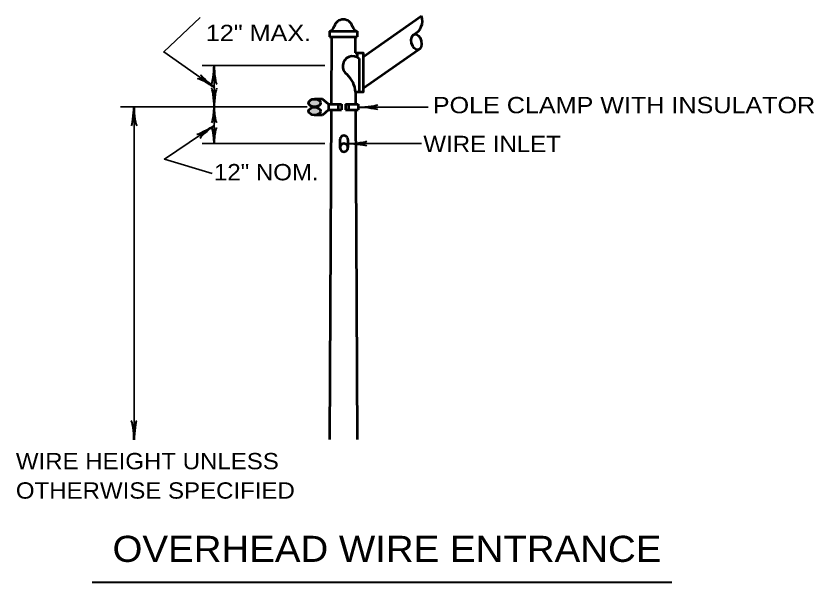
# Model space of a CAD drawing. Extents: x 6488 to 7168, y 276 to 716.
# Drawn here: x 6808.6 to 6930.7, y 441.6 to 528.3 of the extents above; entities that cross this region are included whole.
import ezdxf

# ---------------------------------------------------------------- set-up
doc = ezdxf.new("R2010")
doc.units = 0
doc.layers.add('1', color=7, linetype='Continuous', lineweight=35)

msp = doc.modelspace()

# ---------------------------------------------------------------- hatches: boundary and pattern name
at = {"layer": '1'}
h = msp.add_hatch(color=256, dxfattribs=at)
edge = h.paths.add_edge_path()
edge.add_ellipse((6854.294, 514.969), major_axis=(0.907, 0), ratio=0.6666667, start_angle=0, end_angle=360)
h = msp.add_hatch(color=256, dxfattribs=at)
edge = h.paths.add_edge_path()
edge.add_ellipse((6854.294, 513.717), major_axis=(0.907, 0), ratio=0.6666667, start_angle=0, end_angle=360)

# ---------------------------------------------------------------- linework, layer by layer
at = {"layer": '1', "lineweight": 53}
for p, q in [((6861.725, 522.056), (6870.645, 528.296)), ((6856.586, 525.976), (6860.805, 525.976)), ((6856.586, 525.976), (6856.586, 525.076)), ((6860.805, 525.976), (6860.805, 525.076)), ((6856.586, 525.076), (6860.805, 525.076)), ((6856.885, 525.076), (6856.825, 514.796)), ((6860.506, 525.076), (6860.525, 522.656)), ((6861.725, 517.216), (6870.166, 523.116)), ((6860.825, 522.656), (6860.825, 521.956)), ((6861.126, 521.756), (6861.126, 516.616)), ((6855.506, 515.576), (6854.285, 515.576)), ((6856.425, 514.796), (6855.506, 515.576)), ((6860.546, 516.616), (6860.565, 514.796)), ((6856.425, 514.796), (6858.405, 514.796)), ((6856.425, 514.796), (6856.425, 513.896)), ((6857.905, 514.796), (6857.905, 513.896)), ((6858.405, 514.796), (6858.405, 513.896)), ((6859.006, 514.796), (6860.965, 514.796)), ((6859.006, 514.796), (6859.006, 513.896)), ((6859.485, 514.796), (6859.485, 513.896)), ((6860.965, 514.796), (6860.965, 513.896)), ((6855.506, 513.116), (6854.285, 513.116)), ((6856.425, 513.896), (6855.506, 513.116)), ((6856.425, 513.896), (6858.405, 513.896)), ((6856.825, 513.896), (6856.586, 463.396)), ((6859.006, 513.896), (6860.965, 513.896)), ((6860.565, 513.896), (6860.653, 494.836)), ((6858.166, 509.336), (6858.185, 508.136)), ((6859.385, 509.356), (6859.385, 508.136)), ((6860.666, 494.836), (6860.805, 463.396))]:
    msp.add_line(p, q, dxfattribs=at)
at = {"layer": '1'}
for p, q in [((6855.86, 520.725), (6837.093, 520.725)), ((6853.173, 514.363), (6824.602, 514.363)), ((6826.656, 514.363), (6826.656, 463.396)), ((6861.097, 514.318), (6871.694, 514.318)), ((6855.86, 508.751), (6837.093, 508.751)), ((6859.408, 508.743), (6870.639, 508.743))]:
    msp.add_line(p, q, dxfattribs=at)
at = {"layer": '1', "lineweight": 40}
msp.add_line((6820.262, 441.584), (6908.953, 441.584), dxfattribs=at)
at = {"layer": '1'}
for points in [[(6836.785, 528.081), (6831.219, 522.801), (6838.993, 517.329)], [(6838.92, 508.751), (6838.92, 514.363), (6838.92, 520.725)], [(6838.897, 511.472), (6831.315, 506.384), (6838.609, 504.176)]]:
    msp.add_lwpolyline(points, dxfattribs=at)
at = {"layer": '1', "lineweight": 53}
msp.add_lwpolyline([(6860.525, 522.656), (6861.725, 522.656), (6861.725, 516.616), (6860.546, 516.616)], dxfattribs=at)
for centre, radius, start, end in [((6858.698, 526.299), 1.453, 16.19781, 163.80219), ((6868.526, 527.521), 2.264, 295.32486, 20.09191), ((6856.388, 526.901), 0.936, 281.94387, 347.91984), ((6861.009, 526.901), 0.936, 192.08016, 258.05613), ((6860.13, 520.587), 1.535, 49.39069, 236.15933), ((6856.578, 516.382), 3.982, 3.29768, 47.3671), ((6858.775, 509.36), 0.605, 358.85054, 181.71286), ((6858.781, 508.15), 0.605, 358.85054, 181.71286), ((6858.781, 508.114), 0.605, 178.28714, 1.14946)]:
    msp.add_arc(centre, radius, start, end, dxfattribs=at)
for centre, major_axis, ratio in [((6869.886, 524.309), (-0.27, 1.196), 0.618585), ((6854.294, 514.969), (0.907, 0), 0.666667), ((6854.294, 513.717), (0.907, 0), 0.666667)]:
    msp.add_ellipse(centre, major_axis=major_axis, ratio=ratio, dxfattribs=at)
at = {"layer": '1', "lineweight": 40}
for centre, major_axis, ratio, start_param, end_param in [((6838.711, 519.596), (0.176, 1.756), 0.07063, 3.1407148, 5.41811), ((6839.188, 519.625), (-0.156, 1.786), 0.122415, 0.8963533, 3.1415927), ((6838.198, 518.147), (-1.335, 1.155), 0.07063, 6.2823074, 8.5597026), ((6837.941, 517.731), (1.55, -0.9), 0.122415, 0.8963533, 3.1415927), ((6838.652, 515.463), (0.156, -1.786), 0.122415, 0.8963533, 3.1415927), ((6839.128, 515.493), (-0.176, -1.756), 0.07063, 3.1407148, 5.41811), ((6826.444, 513.243), (0.176, 1.756), 0.07063, 3.1407148, 5.41811), ((6826.444, 513.243), (0.176, 1.756), 0.07063, 3.1407148, 5.41811), ((6826.932, 513.272), (-0.156, 1.786), 0.122415, 0.8963533, 3.1415927), ((6826.932, 513.272), (-0.156, 1.786), 0.122415, 0.8963533, 3.1415927), ((6838.711, 513.233), (0.176, 1.756), 0.07063, 4.6860792, 5.41811), ((6839.191, 513.254), (-0.156, 1.786), 0.122415, 0.8963533, 1.5991095), ((6862.188, 514.594), (-1.786, -0.156), 0.122415, 0.8963533, 3.1415927), ((6862.188, 514.594), (-1.786, -0.156), 0.122415, 0.8963533, 3.1415927), ((6862.218, 514.106), (-1.756, 0.176), 0.07063, 3.1407148, 5.41811), ((6862.218, 514.106), (-1.756, 0.176), 0.07063, 3.1407148, 5.41811), ((6838.76, 513.671), (0.176, 1.756), 0.07063, 3.1407148, 4.4333261), ((6839.142, 513.711), (-0.156, 1.786), 0.122415, 1.8592897, 3.1415927), ((6837.848, 511.024), (1.556, 0.833), 0.07063, 3.1407148, 5.41811), ((6838.145, 510.635), (1.396, 1.125), 0.122415, 0.8963533, 3.1415927), ((6838.76, 509.444), (0.176, -1.756), 0.07063, 1.8498592, 3.1424706), ((6839.142, 509.404), (-0.156, -1.786), 0.122415, 3.1415927, 4.4238957), ((6838.711, 509.881), (0.176, -1.756), 0.07063, 0.8650754, 1.5971061), ((6839.191, 509.861), (-0.156, -1.786), 0.122415, 4.6840758, 5.386832), ((6860.499, 509.019), (-1.786, -0.156), 0.122415, 0.8963533, 3.1415927), ((6860.499, 509.019), (-1.786, -0.156), 0.122415, 0.8963533, 3.1415927), ((6860.529, 508.531), (-1.756, 0.176), 0.07063, 3.1407148, 5.41811), ((6860.529, 508.531), (-1.756, 0.176), 0.07063, 3.1407148, 5.41811), ((6826.379, 464.487), (0.156, -1.786), 0.122415, 0.8963533, 3.1415927), ((6826.379, 464.487), (0.156, -1.786), 0.122415, 0.8963533, 3.1415927), ((6826.867, 464.517), (-0.176, -1.756), 0.07063, 3.1407148, 5.41811), ((6826.867, 464.517), (-0.176, -1.756), 0.07063, 3.1407148, 5.41811)]:
    msp.add_ellipse(centre, major_axis=major_axis, ratio=ratio, start_param=start_param, end_param=end_param, dxfattribs=at)

# ---------------------------------------------------------------- texts
at = {"layer": '1'}
for s, height, width, p in [('12" MAX.', 2.5, 1.15, (6837.649, 524.441)), ('POLE CLAMP WITH INSULATOR', 2.5, 1.15, (6872.391, 513.392)), ('WIRE INLET', 2.5, 1.1, (6870.951, 507.44)), ('12" NOM.', 2.5, 1.1, (6838.897, 503.12)), ('WIRE HEIGHT UNLESS', 2.5, 1.1, (6808.57, 458.859)), ('OTHERWISE SPECIFIED', 2.5, 1.1, (6808.57, 454.359)), ('OVERHEAD WIRE ENTRANCE', 4, 1.1, (6823.365, 444.672))]:
    msp.add_text(s, height=height, dxfattribs=dict(at, width=width)).set_placement(p)

doc.saveas('drawing.dxf')
